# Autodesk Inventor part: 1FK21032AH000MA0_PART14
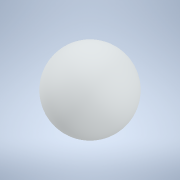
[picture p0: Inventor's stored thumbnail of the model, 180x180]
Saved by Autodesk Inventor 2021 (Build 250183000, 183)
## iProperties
Created: 2025-04
Part Number: 1FK21032AH000MA0_PART14
Material: Generic
Catalog Web Link: www.3dfindit.com
Description: -Servo synchronous motor
Document SubType Name: Modeling
Designer: psAdmin
Mass: 0.113097 g
Surface Area: 1.13097 cm^2
Volume: 0.113097 cm^3
Density: 1 g/cm^3
Appearance: PSOLRGB-212-217-219
Category: PARTsolutions
Title: 1FK21032AH000MA0_PART14
Author: Cadenas PARTsolutions
Comments: Servo synchronous motor
Sending System: PARTsolutions
Preprocessor: ST-DEVELOPER v19.3
PSOL_IDENT_0: {$CADENAS_DATA/23d-libs/siemens_ag/_cat_/45/10/1fk21032ah000ma0.prj},216 {VTYP=3D},{NB=1FK21032AH000
PSOL_IDENT_1: MA0_PART14},{LINA=1FK21032AH000MA0_PART14},{NN=1FK21032AH000MA0_PART14},{NOPRJ=TRUE},{DATE=19.08.202
PSOL_IDENT_2: 5 14:00:35},{GEOMDATE=30.07.2025 02:02:03},{VERSION=},{LINEID=10},{WBVAR=},{WBNUMERIC=}  {NB=1FK2103
PSOL_IDENT_3: 2AH000MA0_PART14},{LINA=1FK21032AH000MA0_PART14},{KT=DUMMY},{PREVIEW=../../../_pool_/14/8e/p_d211_xx
PSOL_IDENT_4: _00426j.png},{DESCSHORT=SIMOTICS S-1FK2 HD, SINAMICS S210 3AC 400V-480V, 0.59 Nm, 4500 rpm},{DESCLON
PSOL_IDENT_5: G=SIMOTICS S-1FK2 HD servo motor M0=0.64 Nm; PN = 0.28 kW at nN=4500 rpm (380-480 V); PN = 0.167 kW
PSOL_IDENT_6: at nN=2500 rpm (200-240 V); degree of protection IP64; cylindrical shaft D14 x 30 mm; absolute encod
PSOL_IDENT_7: er 22-bit + 12-bit multiturn (encoder AM22DQC); with OCC interface; plug size M17, rotatable; SIMOTI
PSOL_IDENT_8: CS S-1FK2 servomotorfor a wide range of uses in industrial environments. SIMOTICS S‑1FK2 servomotors
PSOL_IDENT_9: are compact synchronous motors with a high dynamic performance that set themselves apart as a resul
PSOL_IDENT_10: t of their high power density, degree of protection and overload capability. The motors are availabl
PSOL_IDENT_11: e in two variants: as High Dynamic variant (highest dynamic performance as a result of the low intri
PSOL_IDENT_12: nsic moment of inertia for applications demanding a high dynamic performance with low moved masses)
PSOL_IDENT_13: - and as Compact variant (precise and stable closed-loop control for medium up to large moved masses
PSOL_IDENT_14: as a result of a medium intrinsic moment of inertia). SIMOTICSS‑1FK2 servomotors fully exploit thei
PSOL_IDENT_15: r strengths in a system with the SINAMICSS210 frequency converter and simple connection using the on
PSOL_IDENT_16: e cable connection (OCC). Advantages include the short control and positioning times, fast and preci
PSOL_IDENT_17: se correction of disturbing quantities as well as stable control with a high dynamic performance. Th
PSOL_IDENT_18: e servo motors can be configured to address a wide range of requirements. For example with and witho
PSOL_IDENT_19: ut holding brake, IP64 or IP65 degree of protection, singleturn or multiturn absolute encoders - to
PSOL_IDENT_20: name just a few. Further, the servomotors are available in different shaft heights extending from 20
PSOL_IDENT_21: to 100. A shaft sealing ring is available to achieve an IP65 degree of protection and for subsequen
PSOL_IDENT_22: t mounting at the motor or as spare part. SIMOTICS - the optimum motor for each and every motion con
PSOL_IDENT_23: trol application.},{INTNO=195125335004},{SUPPLIERALTNO=1FK2103-2AH00-0MA0},{MANUID=1FK21032AH000MA0}
PSOL_IDENT_24: ,{MANUNAME=Siemens},{MANUTYPEDESC=SYNCHRONOUS MOTOR 1FK2 HD 0,64 NM},{AAU732=SIMOTICS},{AAO057=S-1FK
PSOL_IDENT_25: 2},{AAU734=SIMOTICS S-1FK2 HD servo motor M0=0.64 Nm; PN = 0.28 kW at nN=4500 rpm (380-480 V); PN =
PSOL_IDENT_26: 0.167 kW at nN=2500 rpm (200-240 V); degree of protection IP64; cylindrical shaft D14 x 30 mm; absol
PSOL_IDENT_27: ute encoder 22-bit + 12-bit multiturn (encoder AM22DQC); with OCC interface; plug size M17, rotatabl
PSOL_IDENT_28: e;},{AAW338=SYNCHRONOUS MOTOR 1FK2 HD 0,64 NM},{AAO742=SIMOTICS},{AAO663=4034106444624},{NOCUPEROU=1
PSOL_IDENT_29: },{PRICEQUANTITY=1},{QUANTITYMIN=1},{QUANTITYINT=1},{CTN=85015100},{COO=RO},{AAO676=1FK2103-2AH00-0M
PSOL_IDENT_30: A0},{AAO677=Siemens AG},{ORDERUNIT=C62},{CONTENTUNIT=C62}
NB: 1FK21032AH000MA0_PART14
NT: Servo synchronous motor
NBSYN: $MANUID._PART14
LINA: 1FK21032AH000MA0_PART14
CATALOG: SIEMENS
PREVIEW: ../../../_pool_/14/8e/p_d211_xx_00426j.png
DESCSHORT: SIMOTICS S-1FK2 HD, SINAMICS S210 3AC 400V-480V, 0.59 Nm, 4500 rpm
DESCLONG: SIMOTICS S-1FK2 HD servo motor M0=0.64 Nm; PN = 0.28 kW at nN=4500 rpm (380-480 V); PN = 0.167 kW at nN=2500 rpm (200-240 V); degree of protection IP64; cylindr
INTNO: 195125335004
SUPPLIERALTNO: 1FK2103-2AH00-0MA0
MANUID: 1FK21032AH000MA0
MANUNAME: Siemens
MANUTYPEDESC: SYNCHRONOUS MOTOR 1FK2 HD 0,64 NM
AAU732: SIMOTICS
AAO057: S-1FK2
AAU734: SIMOTICS S-1FK2 HD servo motor M0=0.64 Nm; PN = 0.28 kW at nN=4500 rpm (380-480 V); PN = 0.167 kW at nN=2500 rpm (200-240 V); degree of protection IP64; cylindr
AAW338: SYNCHRONOUS MOTOR 1FK2 HD 0,64 NM
AAO742: SIMOTICS
AAO663: 4034106444624.0
NOCUPEROU: 1
PRICEQUANTITY: 1
QUANTITYMIN: 1
QUANTITYINT: 1
CTN: 85015100
COO: RO
ARTICLENO: 1FK21032AH000MA0_PART14
BOMINFO: 1FK21032AH000MA0_PART14
CREATOR: CADENAS GmbH
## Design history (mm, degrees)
feature "2025_04_17_15_00_20_0760"
body "Solid1"
